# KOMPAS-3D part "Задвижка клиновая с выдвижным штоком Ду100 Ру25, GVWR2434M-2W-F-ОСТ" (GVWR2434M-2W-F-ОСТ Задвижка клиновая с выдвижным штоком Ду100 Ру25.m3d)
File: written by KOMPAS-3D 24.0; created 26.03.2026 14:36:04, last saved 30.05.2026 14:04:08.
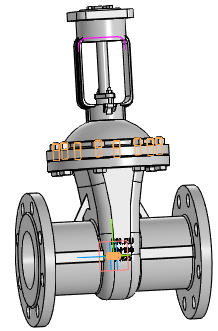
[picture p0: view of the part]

Document properties: Автор: R2D2; Полное имя файла: E:\Работа\Зайцев\GVWR2434M-2W-F-ОСТ Задвижка клиновая с выдвижным штоком DN.ru Ду50-300 Ру25\исходные материалы\DN100\GVWR2434M-2W-F-ОСТ Задвижка клиновая с выдвижным штоком Ду100 Ру25.m3d

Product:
- Component [detail]: ANSI B18.2.4.2M - M5x0,8 - 8  | designation ANSI B18.2.4.2M - M5x0,8  | qty 2  | pos. 2  | Комментарий: Типы метрических   шестигранных гаек   2; Автор: R2D2; additional columns: Сталь, мягкая; source file: ANSI B18.2.4.2M - M5x0,8 ANSI B18.2.4.2M - M5x0,8 - 8.m3d
- Component [detail]: Деталь1  | qty 1  | pos. 3  | additional columns: Типовые; source file: 2.m3d
- Component [detail]: Фланец  | qty 2  | pos. 3  | Автор: R2D2; additional columns: Типовые; source file: Фланец DN100 PN25 b22.m3d
- Component [standard]: Болт М12-6gx50.88.45Г.019 ГОСТ 7798-70  | qty 8  | Материал: Сталь 45Г (density 7850 kg/m3); Масса: 0.06053; Раздел спецификации: Стандартные изделия; Рассекать на разрезах: no; additional columns: BOSimple***Material:39848d99-529e-4aa2-825c-393daa009d15
- Component [standard]: Гайка М12-6H ГОСТ 5915-70  | qty 24  | Масса: 0.0184; Раздел спецификации: Стандартные изделия; Рассекать на разрезах: no
- Component [assembly]: DN50_3D_STEP  | designation Сборка  | qty 1  | pos. 4  | Масса: 2.725126; Автор: R2D2; source file: Фланец А.a3d
- Body: Тело 1  | qty 1
    Масса: 53.338954
- Body: Тело 2  | qty 1
    Масса: 53.338954
- Part/product: Задвижка клиновая с выдвижным штоком Ду100 Ру25  | designation GVWR2434M-2W-F-ОСТ
    Масса: 32
    Раздел спецификации: Прочие изделия
    Примечание: D040-07588

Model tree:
1. Массив по концентрической сетке:1  (labels: Грань.Твердое тело1)  (8 pattern instances)
     Шаг 2 = 360
2. Массив по концентрической сетке:2  (labels: Грань.Твердое тело1)  (2 pattern instances)
     Шаг 2 = 360
3. Элемент выдавливания:1  (with: Грань.Элемент выдавливания:2, Грань.Элемент вращения:1)
     Расстояние 1 = 48.5338
4. Элемент выдавливания:2  (with: Грань.Элемент выдавливания:1, Грань.Элемент вращения:1)
     Расстояние 1 = 42.7931
5. Элемент выдавливания:3  (with: Грань.Элемент выдавливания:1)
     Расстояние 1 = 20
6. Эскиз:1  (with: Вершина.Элемент выдавливания:3, Ребро.Элемент выдавливания:3)
7. Элемент по траектории:1  (with: Грань.Элемент выдавливания:3)
     Толщина стенки 1 = 1; Длина траектории = 116.841
8. Скругление:1  (with: Ребро.Элемент выдавливания:1, Ребро.Элемент выдавливания:2)
     Радиус = 3
9. Элемент выдавливания:4  (with: Грань.Элемент выдавливания:1, Грань.Элемент по траектории:1)
     Расстояние 1 = 88.7998
10. Эскиз:2
11. Элемент выдавливания:5  (with: Грань.Элемент выдавливания:1, Грань.Элемент вращения:1, Грань.Операция без истории:2, Грань.Элемент выдавливания:5)  (labels: Грань.Твердое тело1; Грань.Solid1; Solid1; Твердое тело1)
     Расстояние 1 = 76; Смещение 1 = 1; Расстояние = -150; Ориентация = 2; Расстояние = -430

Referenced files in E:\Работа\Зайцев\GVWR2434M-2W-F-ОСТ Задвижка клиновая с выдвижным штоком DN.ru Ду50-300 Ру25\исходные материалы\DN100\: ANSI B18.2.4.2M - M5x0,8 ANSI B18.2.4.2M - M5x0,8 - 8.m3d, 2.m3d, Фланец А.a3d, Фланец DN100 PN25 b22.m3d
Referenced files in C:\Program Files\ASCON\KOMPAS-3D v24\Libs\PolynomLib\DATA\vault\Methods\Kompas\3D\: PLib_Bolt_1_900.m3d, PLib_Nut_OST92_900.m3d
Referenced files in E:\Работа\Зайцев\GVWR3131M-2W-F-S Задвижка клиновая с выдвижным штоком DN.ru Ду50-200 Ру63\DN100\исходные материалы\: ANSI B18.2.4.2M - M5x0,8 ANSI B18.2.4.2M - M5x0,8 - 8.m3d
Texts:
  BOSimple***PART:25ccc031-f2ed-a43b-e633-090566d53ffa***SHORTLOC:Root±30±20±10±80±10±©{}30±©{BASE}130±290[9;Цинковое, хроматированное;Сталь 45Г ГОСТ 4543-2016;50;12;19;1,75;8.8]
  BOSimple***Material:39848d99-529e-4aa2-825c-393daa009d15
  BOSimple***PART:dfaf85ed-3e43-003f-b29c-9c5b054070d3***SHORTLOC:Root±30±10±20±©{}110±10±50±60[Нет;Без покрытия;Без указания материала;-;12;1,75;19]
  GVWR2434M-2W-F-ОСТ
  DN100
  GOST 26.020 Pr3
  PN25
  ANSI B18.2.4.2M - M5x0,8 ANSI B18.2.4.2M - M5x0,8 - 8 (1)
  Деталь1 Деталь1
  Фланец (1)
  Фланец (2)
  Болт М12-6gx50.88.45Г.019 ГОСТ 7798-70 (1)
  hole1
  hole2
  Гайка М12-6H ГОСТ 5915-70 (1)
  bcut1
  hcut1
  cut1
  Гайка М12-6H ГОСТ 5915-70 (2)
  Гайка М12-6H ГОСТ 5915-70 (3)
  Сборка DN50_3D_STEP
  Ось Z.Начало координат
  Ось Y.Начало координат
  Плоскость ZX.Начало координат
  Плоскость XY.Начало координат
  Plane. Начало координат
